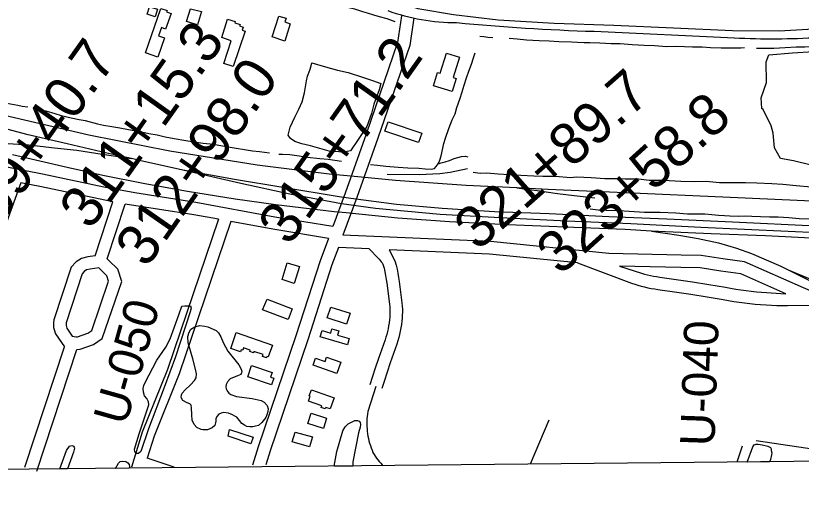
# Model space of a CAD drawing. Extents: x 3625074 to 3663148, y 511451 to 537151.
# Drawn here: x 3636472 to 3638362, y 516860 to 518023 of the extents above; entities that cross this region are included whole.
import ezdxf

# ---------------------------------------------------------------- set-up
doc = ezdxf.new("R2010")
doc.units = 0
for name, color, linetype in [('V-BLDG-OTLN', 7, 'Continuous'), ('V-GRID-FRAM', 7, 'Continuous'), ('V-LEVE-TOET', 7, 'Continuous'), ('V-RAIL-TRAK', 7, 'Continuous'), ('V-RIVR-RANG-IDEN', 7, 'Continuous'), ('V-ROAD-CNTR', 7, 'Continuous'), ('V-SITE-VEGE', 7, 'Continuous'), ('V-SURV-IDEN', 7, 'Continuous'), ('V-TOPO-SHOR', 7, 'Continuous')]:
    doc.layers.add(name, color=color, linetype=linetype)

msp = doc.modelspace()

# ---------------------------------------------------------------- linework, layer by layer
at = {"layer": 'V-BLDG-OTLN'}
for points in [[(3636821.3, 518040.9), (3636836.1, 518036), (3636834.7, 518032.2), (3636845.5, 518028.4), (3636832.4, 517991), (3636822.2, 517994.6), (3636815.2, 517974.8), (3636830.1, 517969.6), (3636813.9, 517923.6), (3636783.8, 517934.2)], [(3636813.2, 518038.7), (3636807.1, 518020.3), (3636788, 518026.7), (3636794.1, 518044.7)], [(3636919.1, 518033.7), (3636908.9, 518000.9), (3636882.7, 518009.1), (3636892.3, 518040.1)], [(3637104.8, 518022.1), (3637122.2, 518017), (3637119.3, 518008.1), (3637132.4, 518003.8), (3637119, 517962.2), (3637088.6, 517972.1)], [(3636990.3, 517962.4), (3636967.7, 517970.4), (3636981.6, 518015.2), (3637000.2, 518009.5), (3636999.1, 518006.2), (3637011.6, 518002), (3637010.5, 517998.8), (3637019.3, 517995.9), (3637016.9, 517988.6), (3637023.6, 517986.4), (3636994.9, 517901), (3636972.2, 517908.6)], [(3637508, 517933.2), (3637539.5, 517923.3), (3637524.5, 517874.6), (3637531.6, 517872.4), (3637522, 517841), (3637477, 517854.9), (3637486.8, 517886.9), (3637493.1, 517885)], [(3637368.1, 517767.6), (3637448.8, 517740.9), (3637441.3, 517718.2), (3637359.8, 517745.3)], [(3637125.3, 517428.7), (3637154.3, 517419.9), (3637141.8, 517379.3), (3637112.8, 517388.3)], [(3637076.6, 517341.3), (3637137.2, 517318.5), (3637127.3, 517292.2), (3637065.3, 517315.6)], [(3637230.1, 517322.2), (3637276.2, 517307.4), (3637267.9, 517281.5), (3637220.9, 517296.6)], [(3637269.9, 517231.3), (3637204.3, 517250.9), (3637208.9, 517266.1), (3637229.7, 517259.9), (3637232.7, 517270), (3637249, 517265.2), (3637246, 517255), (3637274.5, 517246.4)], [(3637002.4, 517260.9), (3637089.3, 517231.1), (3637079.5, 517202.6), (3637076.4, 517203.7), (3637075.2, 517200.3), (3637065.4, 517203.6), (3637066.9, 517208), (3637045.1, 517215.4), (3637044.1, 517212.4), (3637034.8, 517215.6), (3637035.9, 517218.8), (3637019.9, 517224.2), (3637018, 517218.4), (3637014.4, 517219.7), (3637012.6, 517214.5), (3636989.2, 517222.5)], [(3637244.7, 517162.8), (3637187.2, 517182.7), (3637193, 517199.4), (3637216.2, 517191.3), (3637219.9, 517201.8), (3637254.1, 517189.9)], [(3637087.1, 517135.3), (3637030, 517154.4), (3637039.1, 517181.5), (3637088.8, 517164.8), (3637085.1, 517153.6), (3637092.5, 517151.1)], [(3637183.4, 517123), (3637238, 517104), (3637228.7, 517077.3), (3637217.8, 517081.2), (3637216.4, 517077.4), (3637206.8, 517080.8), (3637208.1, 517084.7), (3637176.3, 517095.8), (3637180.5, 517107.9), (3637177.6, 517109)], [(3637182.6, 517067), (3637219.9, 517055.1), (3637212, 517030.3), (3637175, 517042.1)], [(3636986.4, 517027.7), (3637042.8, 517009.5), (3637037.8, 516993.8), (3636982.6, 517011.6)], [(3637144.4, 517021.8), (3637185.8, 517009.9), (3637178.9, 516985.9), (3637137.1, 516997.9)]]:
    msp.add_lwpolyline(points, close=True, dxfattribs=at)
at = {"layer": 'V-GRID-FRAM'}
msp.add_lwpolyline([(3629129.4, 535042.1), (3660791.6, 535359.9), (3660982, 517178), (3629304, 516860), (3629129.4, 535042.1)], dxfattribs=at)
at = {"layer": 'V-LEVE-TOET'}
msp.add_lwpolyline([(3636459.4, 518256.8), (3636618.1, 518214.4), (3636753.6, 518174.2), (3636896.5, 518142.4), (3636944.9, 518133.6), (3636983.7, 518126.6), (3637049.9, 518125), (3637116.3, 518122.4), (3637203.7, 518122.1), (3637253.2, 518115.6), (3637317.8, 518092.2), (3637393.6, 518055.9), (3637439, 518040.5), (3637525.4, 518026.2), (3637633, 518013.5), (3637767.3, 518005.3), (3637910.9, 518000.4), (3638054.5, 517994.1), (3638196.4, 517987.9), (3638309, 517987), (3638460.3, 517996)], dxfattribs=at)
at = {"layer": 'V-RAIL-TRAK'}
for points in [[(3636873.8, 517651.7), (3636769.8, 517675.1), (3636750.5, 517679.5), (3636691.4, 517692.9), (3636595.7, 517715.2), (3636501.7, 517736.6), (3636438.1, 517753.4), (3636378.4, 517770.4), (3636278.9, 517802), (3636212.7, 517822.3)], [(3638423.9, 517575.3), (3638173.5, 517586.7), (3637955.9, 517596), (3637753.4, 517605.5), (3637677.4, 517609), (3637556, 517614.7), (3637385.5, 517627.2), (3637295.2, 517635.6), (3637226.3, 517642), (3637052.6, 517663.7), (3636842.6, 517697.6), (3636647.4, 517736), (3636444.9, 517782.9)], [(3636171.6, 517759.3), (3636265.3, 517742.4), (3636323.9, 517732.4), (3636380.4, 517723.7), (3636441, 517716.8), (3636503.5, 517712.5), (3636565.3, 517705.8), (3636618.9, 517699.7), (3636680.1, 517690.1), (3636750.5, 517679.5)], [(3638417.4, 517486.7), (3638276.1, 517493.7), (3638145, 517498.8), (3638035.5, 517503.2), (3638001.9, 517505.1), (3637938.1, 517508.7), (3637814.6, 517513.4), (3637655.6, 517520.3), (3637515.3, 517527.2), (3637391.6, 517536.1), (3637305.2, 517544.8), (3637266.9, 517548.8), (3637238.3, 517551.8), (3637097.5, 517568.5), (3636999.9, 517582.3), (3636884.8, 517600.6), (3636782.5, 517618.9), (3636681.4, 517639.2), (3636595.6, 517657.9), (3636463.8, 517688.2)], [(3638397.6, 517517.2), (3638196.6, 517526.4), (3638038.8, 517533.5), (3637899.1, 517539.6), (3637755.8, 517546.3), (3637623.8, 517551.7), (3637498, 517559.1), (3637387.9, 517568.8), (3637277.9, 517583.8), (3637250, 517587.6), (3637114.3, 517610.3), (3636998.3, 517629.5), (3636873.8, 517651.7)], [(3640160.3, 517410.3), (3640078.9, 517412.6), (3639890, 517420.6), (3639737.6, 517428.8), (3639547.9, 517444.1), (3639478.6, 517450), (3639288, 517462.1), (3639083.2, 517471), (3638927.7, 517477.2), (3638725.5, 517487.3), (3638540.2, 517494.6), (3638330.9, 517504.4), (3638120.4, 517514), (3637952, 517522.4), (3637798.1, 517529.1), (3637637.6, 517536.9), (3637493.2, 517545), (3637337.5, 517559.8), (3637273.1, 517568.5), (3637255.9, 517570.8), (3637131.1, 517593.6), (3637013.7, 517619.4), (3636873.8, 517651.7)], [(3637365.6, 517642), (3637442.9, 517641.4), (3637492, 517643.5), (3637517.2, 517646.8), (3637559.1, 517656)], [(3637677.4, 517609), (3637726.3, 517602.4), (3637775.4, 517595.6), (3637815.9, 517590.8), (3637865.6, 517585)], [(3638001.9, 517505.1), (3638067.3, 517495.7), (3638113.7, 517487.4), (3638162.8, 517476.9), (3638206.3, 517463.9), (3638242.3, 517451.5), (3638312.8, 517421), (3638330.9, 517411.9), (3638380.4, 517387.1), (3638458.3, 517346.5), (3638464.5, 517343.4), (3638544.4, 517303.5), (3638616.7, 517268), (3638680.5, 517237.2), (3638699.6, 517228), (3638787.2, 517182.1), (3638844.2, 517156.2), (3638876.7, 517142.9), (3638904.9, 517133.3)], [(3638330.9, 517411.9), (3638434.5, 517368.5), (3638503.9, 517343.1), (3638545.3, 517325.9), (3638587.8, 517312.9), (3638635.1, 517301.3), (3638712.6, 517289.2), (3638767.3, 517280.2), (3638871.2, 517264.9), (3638987.7, 517247.1), (3639117, 517227.8), (3639240.6, 517209.1), (3639415.7, 517183.2), (3639511.6, 517164.8), (3639571.3, 517155.7), (3639658.4, 517148.3)]]:
    msp.add_lwpolyline(points, dxfattribs=at)
at = {"layer": 'V-ROAD-CNTR'}
for points in [[(3637400.3, 518022.7), (3637390.8, 517958.6), (3637315, 517738.5), (3637264.3, 517596.5), (3637234.8, 517516.3)], [(3637430, 518018.3), (3637420.1, 517951.4), (3637343.3, 517728.6), (3637292.6, 517586.3), (3637259.1, 517495.3)], [(3637863.9, 517985.7), (3638201, 517970)], [(3637234.8, 517516.3), (3637095.4, 517539), (3636905, 517574.1), (3636758.1, 517597), (3636683.9, 517610.9), (3636536, 517641.7), (3636404.3, 517667.6), (3636221.5, 517705.5), (3636166, 517717.7), (3636114, 517728.7)], [(3636484.1, 517621.3), (3636383.9, 517346), (3636284.1, 517058.6), (3636240.1, 516924.8)], [(3636705.5, 517575.8), (3636530.1, 517612.3), (3636484.1, 517621.3)], [(3636618.5, 517220.4), (3636627.2, 517221.4), (3636659, 517232.6), (3636680.1, 517246.4), (3636726.9, 517384.1), (3636717.8, 517413.6), (3636696.2, 517434.5), (3636692.2, 517438.1), (3636735.2, 517570.2)], [(3636663.2, 517445.6), (3636705.5, 517575.8)], [(3636959.4, 517533.6), (3636900, 517544.6), (3636735.2, 517570.2)], [(3636959.4, 517533.6), (3636837.2, 517172.4), (3636776.3, 517021.5), (3636750.1, 516937.3)], [(3636989.3, 517528.1), (3636865.3, 517162), (3636804.6, 517011.5), (3636788.3, 516959.3)], [(3637224.3, 517487.7), (3637090.3, 517509.5), (3636989.3, 517528.1)], [(3638616.2, 517262.2), (3638367.2, 517368.6), (3638225.2, 517431.5), (3638173, 517438.6), (3638121.1, 517446.8), (3638072.7, 517447.3), (3637899.2, 517451), (3637614.3, 517479.8), (3637259.1, 517495.3)], [(3637224.3, 517487.7), (3637204.4, 517433.6), (3637146.1, 517253), (3637055.5, 516986.1), (3637041.8, 516942.4)], [(3637248.2, 517465.8), (3637232.8, 517423.8), (3637174.6, 517243.6), (3637084.1, 516976.8), (3637073.5, 516943.3)], [(3637322.6, 517462.5), (3637248.2, 517465.8)], [(3637322.6, 517462.5), (3637344.3, 517440.1), (3637346.7, 517437.4), (3637349, 517434.5), (3637351.2, 517431.5), (3637353.2, 517428.4), (3637355, 517425.2), (3637356.1, 517423.2), (3637358.1, 517415.8), (3637360.1, 517407), (3637361.9, 517398.1), (3637363.5, 517389.1), (3637364.9, 517380.1), (3637371.3, 517329.1), (3637371.9, 517322.9), (3637372.1, 517316.6), (3637372.2, 517310.3), (3637372.1, 517304), (3637371.7, 517297.7), (3637371.1, 517291.3), (3637370.2, 517284.3), (3637369.1, 517277.3), (3637367.8, 517270.4), (3637366.3, 517263.5), (3637364.6, 517256.7), (3637362.6, 517249.9), (3637360.4, 517243.2), (3637352.4, 517220.9), (3637344.5, 517198.3), (3637336.8, 517175.5), (3637329.4, 517152.7), (3637324.1, 517135.7)], [(3637370.5, 517460.4), (3637384.3, 517434), (3637387.2, 517423), (3637389.4, 517413.4), (3637391.4, 517403.7), (3637393.1, 517393.9), (3637394.6, 517384.2), (3637401.2, 517332.2), (3637401.8, 517324.8), (3637402.1, 517317.4), (3637402.2, 517310), (3637402, 517302.7), (3637401.6, 517295.3), (3637400.9, 517288.1), (3637399.9, 517280.2), (3637398.7, 517272.3), (3637397.2, 517264.4), (3637395.5, 517256.6), (3637393.5, 517248.8), (3637391.3, 517241.1), (3637388.8, 517233.5), (3637380.7, 517210.9), (3637372.9, 517188.5), (3637365.3, 517166.1), (3637358, 517143.6), (3637352.7, 517126.7)], [(3637823.8, 517428.4), (3637612.1, 517449.9), (3637370.5, 517460.4)], [(3636663.2, 517445.6), (3636645.5, 517443.5), (3636629.9, 517439.5), (3636617, 517430.8), (3636605.1, 517418.5), (3636563.8, 517291.3), (3636562.9, 517284.3), (3636563, 517273), (3636567.8, 517258.4), (3636588.9, 517226.7)], [(3636671.7, 517416.4), (3636651, 517413.9), (3636642.3, 517411.7), (3636636.4, 517407.8), (3636631.6, 517402.7), (3636593.2, 517284.8), (3636592.9, 517282.6), (3636592.9, 517278), (3636595, 517271.7), (3636607.7, 517252.7)], [(3636607.7, 517252.7), (3636617, 517250.5), (3636620.4, 517250.9), (3636645.6, 517259.7), (3636655, 517265.9), (3636695.3, 517384.5), (3636691.4, 517397.4), (3636671.7, 517416.4)], [(3637823.8, 517428.4), (3637953.4, 517380.1), (3637961.2, 517377.5), (3637969.1, 517375), (3637977, 517372.8), (3637985, 517370.7), (3637993.1, 517368.9), (3638001.2, 517367.3), (3638009.3, 517365.9), (3638017.2, 517364.8), (3638056.6, 517359), (3638095.9, 517353.1), (3638135.2, 517347), (3638174.3, 517340.7), (3638186.8, 517338.3), (3638199.6, 517336.1), (3638212.5, 517334.1), (3638225.4, 517332.4), (3638238.3, 517330.8), (3638251.3, 517329.5), (3638264.2, 517328.4), (3638277.2, 517327.5), (3638290.2, 517326.9), (3638303.2, 517326.4), (3638316.2, 517326.2), (3638329.2, 517326.2), (3638387.6, 517327.2)], [(3638325.2, 517354.3), (3638216.9, 517402.3), (3638168.6, 517408.9), (3638118.6, 517416.8), (3638072.2, 517417.3), (3637924.3, 517420.4)], [(3637924.3, 517420.4), (3637977.6, 517403.8), (3637984.8, 517401.7), (3637992, 517399.9), (3637999.3, 517398.2), (3638006.6, 517396.8), (3638013.9, 517395.6), (3638021.5, 517394.5), (3638061, 517388.7), (3638100.5, 517382.8), (3638139.9, 517376.6), (3638179.5, 517370.2), (3638192.1, 517367.8), (3638204.5, 517365.7), (3638216.8, 517363.8), (3638229.2, 517362.1), (3638241.6, 517360.7), (3638254.1, 517359.4), (3638266.5, 517358.3), (3638325.2, 517354.3)], [(3636494.1, 516937), (3636588.9, 517226.7)], [(3636522.6, 516927.7), (3636618.5, 517220.4)], [(3637338.4, 517131.2), (3637319, 517070.8), (3637318.1, 517064.9), (3637317.4, 517059.1), (3637317, 517053.2), (3637316.7, 517047.3), (3637316.6, 517041.4), (3637316.8, 517035.5), (3637317.1, 517029.6), (3637317.7, 517023.7), (3637318.4, 517017.8), (3637319.3, 517012), (3637320.5, 517006.2), (3637321.8, 517000.5), (3637323.4, 516994.8), (3637325.1, 516989.1), (3637327, 516983.5), (3637329.2, 516978), (3637331.5, 516972.6), (3637334.1, 516968), (3637336.9, 516963.5), (3637339.9, 516959.2), (3637343.1, 516955), (3637346.5, 516950.9), (3637350, 516947), (3637353.7, 516943.2), (3637356.2, 516940.9)], [(3636853.3, 516937.5), (3636788.3, 516959.3)]]:
    msp.add_lwpolyline(points, dxfattribs=at)
for centre, radius, start, end in [((3637535.3, 518514.6), 508, 250.6312, 269.6827), ((3638011.4, 522945.5), 4962, 264.4637, 268.2968), ((3638291.1, 519911.5), 1943.7, 267.3414, 273.323)]:
    msp.add_arc(centre, radius, start, end, dxfattribs=at)
at = {"layer": 'V-SITE-VEGE'}
for p, q in [((3637264.2, 517034.3), (3637271.7, 517041.3)), ((3637271.7, 517041.3), (3637281, 517046.1)), ((3637281, 517046.1), (3637287.6, 517049.7)), ((3637287.6, 517049.7), (3637291.7, 517049.9)), ((3637291.7, 517049.9), (3637294.6, 517049.5)), ((3637294.6, 517049.5), (3637298.1, 517047.9)), ((3637298.1, 517047.9), (3637300.8, 517044.8)), ((3637301.5, 517040.1), (3637300.5, 517033.5)), ((3637300.8, 517044.8), (3637301.5, 517040.1)), ((3637244.5, 516974.7), (3637258.6, 517024.5)), ((3637258.6, 517024.5), (3637264.2, 517034.3)), ((3637296.3, 517020), (3637282.9, 516950.1)), ((3637300.5, 517033.5), (3637296.3, 517020)), ((3636594.3, 516977), (3636601.4, 516987.8)), ((3636601.4, 516987.8), (3636607, 516989.7)), ((3636607, 516989.7), (3636609.1, 516988.9)), ((3636609.1, 516988.9), (3636611, 516987.7)), ((3636611, 516987.7), (3636612.6, 516985.4)), ((3636612.9, 516983.1), (3636611.1, 516973.6)), ((3636612.6, 516985.4), (3636612.9, 516983.1)), ((3638232.1, 516949.7), (3638245.3, 516986.1)), ((3638245.3, 516986.1), (3638248.6, 516990.7)), ((3638248.6, 516990.7), (3638253.6, 516992.8)), ((3638253.6, 516992.8), (3638258.5, 516993)), ((3638258.5, 516993), (3638267.9, 516991.3)), ((3638267.9, 516991.3), (3638281.4, 516988)), ((3638281.4, 516988), (3638287.8, 516984.5)), ((3638287.8, 516984.5), (3638289.3, 516981.2)), ((3638289.3, 516981.2), (3638289.8, 516977.3)), ((3636577.7, 516933.1), (3636594.3, 516977)), ((3636611.1, 516973.6), (3636596.5, 516933.2)), ((3637238.2, 516939.7), (3637244.5, 516974.7)), ((3638290.7, 516967.1), (3638288, 516955.7)), ((3638289.8, 516977.3), (3638290.8, 516971.5)), ((3638290.8, 516971.5), (3638290.7, 516967.1)), ((3636711.9, 516934.4), (3636719.3, 516947)), ((3636719.3, 516947), (3636723.2, 516950.6)), ((3636723.2, 516950.6), (3636729, 516952.1)), ((3636729, 516952.1), (3636736.4, 516950.7)), ((3636736.4, 516950.7), (3636741.6, 516948)), ((3636741.6, 516948), (3636744.5, 516943.9)), ((3636744.5, 516943.9), (3636745.6, 516939.3)), ((3637282.9, 516950.1), (3637282.9, 516940.1)), ((3638285.8, 516950.2), (3638232.1, 516949.7)), ((3638288, 516955.7), (3638285.8, 516950.2)), ((3636596.5, 516933.2), (3636577.7, 516933.1)), ((3636744.7, 516934.7), (3636711.9, 516934.4)), ((3636745.6, 516939.3), (3636744.7, 516934.7)), ((3637282.9, 516940.1), (3637238.2, 516939.7))]:
    msp.add_line(p, q, dxfattribs=at)
msp.add_lwpolyline([(3638385.9, 517663.4), (3638343.2, 517674.4), (3638311.9, 517680), (3638297.6, 517705.4), (3638294.1, 517740.5), (3638289.6, 517758.2), (3638270, 517797.3), (3638267, 517800.4), (3638265.7, 517825.6), (3638278.2, 517862.9), (3638277.8, 517912.6), (3638284, 517929.4), (3638340.6, 517934.3), (3638391.1, 517937)], dxfattribs=at)
for points in [[(3637184.7, 517910), (3637217.1, 517900.6), (3637245.7, 517892), (3637272.1, 517886.8), (3637306, 517875.1), (3637330.4, 517867.2), (3637350.6, 517859.8), (3637346.6, 517844.6), (3637333.4, 517810.7), (3637327.5, 517788.2), (3637316.6, 517756.9), (3637302.2, 517735.2), (3637295.7, 517725.7), (3637277.1, 517698.4), (3637261.1, 517694.7), (3637226.3, 517697.6), (3637181.3, 517710.6), (3637160.3, 517714.9), (3637143.2, 517720.4), (3637133.3, 517728.1), (3637127.2, 517736.2), (3637132, 517754.9), (3637143.2, 517779.3), (3637152.9, 517798.7), (3637160.7, 517815.8), (3637166.6, 517837.5), (3637169, 517852), (3637171.8, 517866.9), (3637174.2, 517877.6), (3637179.3, 517892.5), (3637182.4, 517902.8)], [(3636891.8, 517311.3), (3636856, 517202.3), (3636828.9, 517129.2), (3636791.4, 517029.7), (3636773, 516975.3), (3636767, 516970.1), (3636762.9, 516970.5), (3636759.6, 516972.7), (3636758.8, 516974.4), (3636757.5, 516980.6), (3636769, 517017.2), (3636792.2, 517086.9), (3636791.6, 517094.5), (3636787.4, 517102.1), (3636781.6, 517109.1), (3636779, 517117.5), (3636778.4, 517126.4), (3636780.4, 517133.7), (3636783.2, 517141.3), (3636811.7, 517195), (3636833.2, 517225.9), (3636843.4, 517246.1), (3636864.4, 517303.7), (3636871.5, 517324.3), (3636879.1, 517325.7), (3636892.1, 517325.2), (3636893.6, 517319.5)], [(3636951.2, 517037.9), (3636944.6, 517031.6), (3636933.5, 517027.2), (3636929, 517026.8), (3636922.3, 517027.2), (3636917.8, 517028), (3636907.8, 517032.6), (3636901.4, 517039.6), (3636896.4, 517050.6), (3636895.4, 517063.4), (3636895.1, 517079.9), (3636894, 517086.6), (3636891.1, 517089.4), (3636884.1, 517092.3), (3636874.3, 517097.8), (3636870.2, 517105), (3636870.9, 517111), (3636872.6, 517115.5), (3636879.3, 517123.4), (3636892, 517135.3), (3636901.7, 517145.9), (3636906, 517151.9), (3636906.9, 517161.4), (3636904.4, 517172.8), (3636898, 517198.1), (3636886.8, 517236.7), (3636885.9, 517251.2), (3636889.1, 517262.3), (3636893, 517269.2), (3636902.5, 517274.6), (3636914.8, 517277.8), (3636927.2, 517276.2), (3636933.9, 517275.1), (3636954.2, 517265.7), (3636960, 517260.2), (3636965.2, 517250.7), (3636970.7, 517237.1), (3636982, 517216.5), (3637008.4, 517183.8), (3637014.5, 517172.7), (3637015.8, 517167.4), (3637015.2, 517164), (3637013.2, 517160.3), (3637005.3, 517157.2), (3636987.6, 517149.4), (3636981, 517142.3), (3636978.2, 517136.5), (3636977.4, 517130.5), (3636977.9, 517125.6), (3636980.2, 517120.6), (3636984.7, 517114.9), (3636989.5, 517112), (3637003.2, 517107.5), (3637040.6, 517102.4), (3637062.3, 517097.6), (3637069.8, 517093.6), (3637077.1, 517086), (3637079.2, 517077.7), (3637078.2, 517070.9), (3637075.8, 517063.2), (3637073.4, 517056.6), (3637063.8, 517044.7), (3637055.7, 517037.9), (3637049.1, 517035.8), (3637042.3, 517034.1), (3637034.9, 517034), (3637028.3, 517035.4), (3637022.3, 517038.3), (3637016.2, 517042.6), (3637010, 517049.3), (3637006.7, 517053.6), (3637003.5, 517057.5), (3636999.4, 517060.2), (3636993.4, 517062.9), (3636984.1, 517067.5), (3636972.1, 517068.5), (3636966.1, 517067.4), (3636960.9, 517064.5), (3636956, 517059.5), (3636953.6, 517053.9), (3636953.6, 517048.1), (3636952.8, 517044.2)]]:
    msp.add_lwpolyline(points, close=True, dxfattribs=at)
at = {"layer": 'V-TOPO-SHOR'}
for points in [[(3637225.4, 518054.7), (3637236.3, 518053.2), (3637250.6, 518048.5), (3637270.1, 518043.6), (3637286.6, 518039.5), (3637306.5, 518033.7), (3637317.4, 518030.5), (3637332.7, 518025.2), (3637346.4, 518021.7), (3637364.5, 518016.4), (3637384.3, 518009.2)], [(3637588.2, 517974.2), (3637597.8, 517972.8), (3637608.1, 517971.5), (3637619.7, 517970.8)], [(3637659.3, 517969.5), (3637678.2, 517967.2), (3637700.5, 517965.4), (3637731.1, 517963.4), (3637755.2, 517962.4), (3637778.9, 517961.4), (3637809, 517960)], [(3637809, 517960), (3637823.3, 517959.3), (3637840, 517959), (3637853, 517958.9), (3637877.1, 517957.9), (3637904.5, 517956.3), (3637926.5, 517956.5), (3637955.5, 517954.1), (3637984.4, 517952.5), (3638008.7, 517951.5), (3638037.9, 517949.5), (3638059.6, 517949.7), (3638081.3, 517949), (3638100.5, 517948.4), (3638123.8, 517948.2), (3638143.9, 517946.7), (3638169, 517946.3), (3638192.1, 517945.9), (3638216.8, 517945.9), (3638225.1, 517947.1)], [(3638254.6, 517944.9), (3638271.3, 517944.9), (3638296.4, 517944.9), (3638322.9, 517946.7), (3638350, 517948.1), (3638370.5, 517948.6), (3638403.8, 517949.1), (3638430.9, 517950.1), (3638458.8, 517949.5), (3638489.5, 517952.4), (3638520.1, 517953.6), (3638542.8, 517954), (3638577.9, 517954.9), (3638603.6, 517957.5)], [(3637325.8, 517665), (3637342.5, 517663.4), (3637362.4, 517661.5), (3637391.9, 517658.9), (3637415.5, 517656.9), (3637441.8, 517656.3), (3637457.4, 517654.6), (3637471.7, 517653.7), (3637479.3, 517655.6), (3637483.7, 517660.6), (3637488.7, 517667.1), (3637492.4, 517675.8), (3637495.4, 517686.2), (3637501.8, 517716), (3637505.9, 517728.5), (3637514.3, 517752.2), (3637522.2, 517773), (3637528.9, 517787.3), (3637533.6, 517802.8), (3637540.3, 517822.3), (3637545.8, 517839.8), (3637551.1, 517856.4), (3637556.6, 517873.5), (3637562.3, 517890.2), (3637568.2, 517906.5), (3637573.1, 517921.6), (3637577.6, 517933.7)], [(3636217, 517868.4), (3636237.1, 517863.8), (3636270.7, 517856), (3636301.3, 517849), (3636331.7, 517842), (3636359.6, 517835.6), (3636390, 517827.2), (3636412.4, 517822.1), (3636441.9, 517814.7), (3636476.5, 517808.1), (3636487.2, 517805.6), (3636501.3, 517804.3)], [(3636517.6, 517800.4), (3636544.1, 517794.4), (3636565.9, 517787.9), (3636581.2, 517783), (3636605.5, 517777.2), (3636624.6, 517773.3), (3636639.3, 517771.2), (3636668.5, 517763.4), (3636683.4, 517759.9), (3636703.1, 517756.7), (3636722.4, 517753.8), (3636743.1, 517749.9), (3636774.5, 517744), (3636792.2, 517740.1), (3636812.5, 517736.8), (3636831.4, 517732.1), (3636853.3, 517728.1), (3636881.3, 517723.3), (3636901.2, 517720), (3636922.9, 517716.6), (3636948, 517714.4), (3636969.2, 517710.5), (3637002.3, 517704.9), (3637022.3, 517701.1), (3637041.2, 517698.4), (3637058.6, 517696.3), (3637082.2, 517693.3)], [(3637104.9, 517690.3), (3637113.5, 517689.9), (3637131.2, 517689.2), (3637154.1, 517685.8), (3637174.2, 517683), (3637203.6, 517679.4), (3637223.7, 517678.3), (3637255.6, 517673.7)], [(3637488.7, 517667.1), (3637495.9, 517669.1), (3637504.9, 517671.8), (3637515.5, 517675.1), (3637526.5, 517679.6), (3637536, 517682.3), (3637544.6, 517684.6), (3637554.2, 517685.3), (3637559.9, 517683.7)], [(3637572.4, 517646.6), (3637589.7, 517644.6), (3637605.5, 517645.5), (3637632.3, 517642.5), (3637659.4, 517641.5), (3637687.5, 517639.3), (3637718.9, 517638.1), (3637740.2, 517637.3), (3637770.5, 517637.5), (3637806.5, 517634.4), (3637820.9, 517635.5), (3637856.3, 517633.8), (3637889.2, 517632), (3637923.2, 517631.3), (3637938.6, 517631.2), (3637970.2, 517630.6), (3637996.1, 517627.8), (3638030.9, 517627.9), (3638071.9, 517625.6), (3638105, 517624.8), (3638132.9, 517625.2), (3638164.9, 517622.3), (3638196, 517622.1), (3638228.1, 517621.7), (3638255.1, 517621.5), (3638291, 517619.8), (3638317.5, 517617.8), (3638349.5, 517615.2), (3638386.1, 517611.9)], [(3637854.3, 517558.8), (3637873.4, 517556.5), (3637892.4, 517555.7), (3637922.8, 517554.3), (3637948.3, 517552.9), (3637984.5, 517550.7), (3638022.4, 517551), (3638059.8, 517548.9), (3638088.3, 517546.7), (3638114.5, 517546.3), (3638129.7, 517546.6), (3638147, 517545.2), (3638162.9, 517543.7), (3638177.3, 517542.4), (3638190.4, 517541.9), (3638211.1, 517541.2), (3638226.8, 517541.7), (3638243.4, 517540.7), (3638263.7, 517540.6), (3638285.6, 517539.8), (3638306.1, 517539.7), (3638331.8, 517537.9), (3638356.8, 517535.3), (3638385.9, 517534.7)], [(3637754.3, 517050.5), (3637709.5, 516944.4)], [(3638571.1, 516953.1), (3638431.5, 516974.4), (3638253.5, 517000.9)], [(3638219.6, 516987.8), (3638206.9, 516949.4)]]:
    msp.add_lwpolyline(points, dxfattribs=at)

# ---------------------------------------------------------------- texts
at = {"layer": 'V-RIVR-RANG-IDEN'}
for s, rotation, p in [('U-050', 74.2505, (3636737.3, 517034.9)), ('U-040', 88.0223, (3638153.1, 516986.7))]:
    msp.add_text(s, height=83, rotation=rotation, dxfattribs=at).set_placement(p)
at = {"layer": 'V-SURV-IDEN'}
for s, rotation, p in [('311+15.3', 54.516, (3636651.7, 517505.2)), ('309+40.7', 54.6701, (3636393.6, 517460.8)), ('315+71.2', 54.695, (3637130.2, 517467)), ('312+98.0', 55.1782, (3636787, 517413.9)), ('321+89.7', 41.3502, (3637583.2, 517455.5)), ('323+58.8', 42.0708, (3637782.2, 517396.6))]:
    msp.add_text(s, height=100, rotation=rotation, dxfattribs=at).set_placement(p)

doc.saveas('drawing.dxf')
